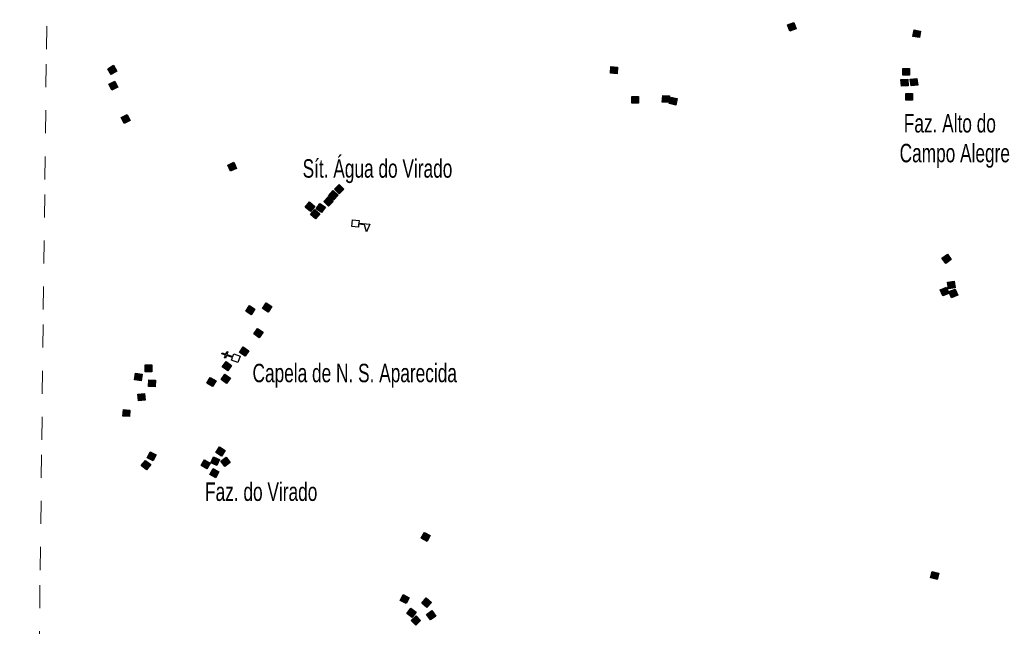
# Model space of a CAD drawing. Extents: x 679 to 705, y 7427.4 to 7455.4.
# Drawn here: x 679.037 to 683.329, y 7434.793 to 7437.424 of the extents above; entities that cross this region are included whole.
import ezdxf

# ---------------------------------------------------------------- set-up
doc = ezdxf.new("R2010")
doc.units = 0
doc.header["$LTSCALE"] = 0.032
doc.linetypes.add('SHORT_DASHED', pattern=[2.7, 1.5, -1.2])
for name, color, linetype, lineweight in [('2', 7, 'Continuous', 25), ('4', 7, 'Continuous', 25), ('58', 7, 'SHORT_DASHED', 13), ('6', 7, 'Continuous', 25)]:
    doc.layers.add(name, color=color, linetype=linetype, lineweight=lineweight)
doc.layers.add('61', color=7, linetype='Continuous')

msp = doc.modelspace()

# ---------------------------------------------------------------- hatches: boundary and pattern name
at = {"layer": '2'}
for points in [[(682.3948, 7437.4121), (682.4052, 7437.385), (682.3782, 7437.3746), (682.3678, 7437.4017)], [(682.9449, 7437.3754), (682.9402, 7437.3468), (682.9116, 7437.3516), (682.9163, 7437.3802)], [(679.4441, 7437.2268), (679.4588, 7437.2019), (679.4338, 7437.1871), (679.4191, 7437.2121)], [(681.6306, 7437.2192), (681.628, 7437.1903), (681.5991, 7437.193), (681.6018, 7437.2218)], [(682.8967, 7437.2135), (682.8967, 7437.1845), (682.8677, 7437.1845), (682.8677, 7437.2135)], [(682.8887, 7437.1666), (682.8907, 7437.1377), (682.8618, 7437.1356), (682.8597, 7437.1645)], [(682.9002, 7437.1664), (682.929, 7437.1697), (682.9323, 7437.1409), (682.9035, 7437.1376)], [(679.45, 7437.1575), (679.4624, 7437.1312), (679.4362, 7437.1188), (679.4238, 7437.145)], [(681.7208, 7437.0912), (681.7208, 7437.0622), (681.6918, 7437.0622), (681.6918, 7437.0912)], [(681.8551, 7437.0944), (681.8532, 7437.0655), (681.8243, 7437.0674), (681.8262, 7437.0964)], [(681.8894, 7437.0821), (681.8828, 7437.0539), (681.8546, 7437.0604), (681.8611, 7437.0887)], [(682.9094, 7437.1038), (682.9094, 7437.0748), (682.8804, 7437.0748), (682.8804, 7437.1038)], [(679.5032, 7437.0127), (679.5158, 7436.9866), (679.4897, 7436.974), (679.4771, 7437.0001)], [(679.9661, 7436.8058), (679.9779, 7436.7793), (679.9514, 7436.7675), (679.9396, 7436.794)], [(680.4223, 7436.7096), (680.4431, 7436.6893), (680.4228, 7436.6685), (680.4021, 7436.6888)], [(680.3757, 7436.6561), (680.3967, 7436.6361), (680.3767, 7436.6151), (680.3557, 7436.6351)], [(680.396, 7436.6828), (680.4178, 7436.6636), (680.3987, 7436.6419), (680.3769, 7436.661)], [(680.2946, 7436.6336), (680.3166, 7436.6147), (680.2977, 7436.5927), (680.2757, 7436.6115)], [(680.3391, 7436.6277), (680.3629, 7436.6111), (680.3463, 7436.5873), (680.3225, 7436.6039)], [(680.3174, 7436.6012), (680.3391, 7436.5821), (680.3199, 7436.5603), (680.2982, 7436.5795)], [(683.0609, 7436.4071), (683.0778, 7436.3835), (683.0542, 7436.3666), (683.0373, 7436.3902)], [(683.0566, 7436.264), (683.0679, 7436.2372), (683.0411, 7436.226), (683.0299, 7436.2527)], [(683.0901, 7436.29), (683.0949, 7436.2614), (683.0663, 7436.2565), (683.0615, 7436.2851)], [(683.0948, 7436.2554), (683.1057, 7436.2286), (683.0788, 7436.2176), (683.0679, 7436.2445)], [(680.0335, 7436.1845), (680.0575, 7436.1682), (680.0412, 7436.1442), (680.0172, 7436.1605)], [(680.1057, 7436.1955), (680.1304, 7436.1804), (680.1153, 7436.1556), (680.0905, 7436.1707)], [(680.0689, 7436.0847), (680.0927, 7436.068), (680.076, 7436.0443), (680.0523, 7436.061)], [(680.0066, 7436.0045), (680.0308, 7435.9884), (680.0147, 7435.9642), (679.9906, 7435.9803)], [(679.6097, 7435.9263), (679.6097, 7435.8973), (679.5807, 7435.8973), (679.5807, 7435.9263)], [(679.933, 7435.9414), (679.9564, 7435.9242), (679.9392, 7435.9008), (679.9159, 7435.918)], [(679.5677, 7435.8867), (679.5643, 7435.8579), (679.5355, 7435.8613), (679.5389, 7435.8901)], [(679.9273, 7435.8865), (679.9508, 7435.8695), (679.9338, 7435.846), (679.9103, 7435.863)], [(679.6258, 7435.861), (679.6244, 7435.832), (679.5955, 7435.8334), (679.5968, 7435.8623)], [(679.8638, 7435.8721), (679.8887, 7435.8572), (679.8738, 7435.8323), (679.8489, 7435.8471)], [(679.5789, 7435.8023), (679.5815, 7435.7735), (679.5526, 7435.7708), (679.55, 7435.7997)], [(679.5154, 7435.7309), (679.5126, 7435.7021), (679.4838, 7435.7048), (679.4866, 7435.7337)], [(679.6029, 7435.5496), (679.6286, 7435.5363), (679.6153, 7435.5105), (679.5895, 7435.5239)], [(679.9042, 7435.5713), (679.9283, 7435.5552), (679.9123, 7435.5311), (679.8881, 7435.5471)], [(679.5825, 7435.5125), (679.6053, 7435.4946), (679.5875, 7435.4718), (679.5646, 7435.4896)], [(679.8389, 7435.5149), (679.8636, 7435.4996), (679.8484, 7435.475), (679.8237, 7435.4902)], [(679.877, 7435.5281), (679.9036, 7435.5166), (679.8921, 7435.4899), (679.8655, 7435.5014)], [(679.9332, 7435.5266), (679.9506, 7435.5033), (679.9274, 7435.486), (679.91, 7435.5092)], [(679.8757, 7435.4766), (679.9013, 7435.4629), (679.8876, 7435.4373), (679.862, 7435.451)], [(680.7923, 7435.1998), (680.8178, 7435.1861), (680.8041, 7435.1605), (680.7786, 7435.1742)], [(682.9956, 7435.0305), (683.0237, 7435.0231), (683.0163, 7434.9951), (682.9883, 7435.0024)], [(680.7008, 7434.9298), (680.7265, 7434.9162), (680.7129, 7434.8906), (680.6873, 7434.9041)], [(680.8006, 7434.9152), (680.8226, 7434.8963), (680.8037, 7434.8743), (680.7817, 7434.8932)], [(680.7331, 7434.8714), (680.7565, 7434.8542), (680.7393, 7434.8309), (680.7159, 7434.8481)], [(680.8247, 7434.8603), (680.8419, 7434.8369), (680.8185, 7434.8197), (680.8013, 7434.8431)], [(680.7563, 7434.8379), (680.7762, 7434.8168), (680.755, 7434.7969), (680.7352, 7434.8181)]]:
    msp.add_hatch(color=256, dxfattribs=at).paths.add_polyline_path(points)

# ---------------------------------------------------------------- linework, layer by layer
for points in [[(682.3948, 7437.4121), (682.4052, 7437.385), (682.3782, 7437.3746), (682.3678, 7437.4017)], [(682.9449, 7437.3754), (682.9402, 7437.3468), (682.9116, 7437.3516), (682.9163, 7437.3802)], [(679.4441, 7437.2268), (679.4588, 7437.2019), (679.4338, 7437.1871), (679.4191, 7437.2121)], [(681.6306, 7437.2192), (681.628, 7437.1903), (681.5991, 7437.193), (681.6018, 7437.2218)], [(682.8967, 7437.2135), (682.8967, 7437.1845), (682.8677, 7437.1845), (682.8677, 7437.2135)], [(682.8887, 7437.1666), (682.8907, 7437.1377), (682.8618, 7437.1356), (682.8597, 7437.1645)], [(682.9002, 7437.1664), (682.929, 7437.1697), (682.9323, 7437.1409), (682.9035, 7437.1376)], [(679.45, 7437.1575), (679.4624, 7437.1312), (679.4362, 7437.1188), (679.4238, 7437.145)], [(681.7208, 7437.0912), (681.7208, 7437.0622), (681.6918, 7437.0622), (681.6918, 7437.0912)], [(681.8551, 7437.0944), (681.8532, 7437.0655), (681.8243, 7437.0674), (681.8262, 7437.0964)], [(681.8894, 7437.0821), (681.8828, 7437.0539), (681.8546, 7437.0604), (681.8611, 7437.0887)], [(682.9094, 7437.1038), (682.9094, 7437.0748), (682.8804, 7437.0748), (682.8804, 7437.1038)], [(679.5032, 7437.0127), (679.5158, 7436.9866), (679.4897, 7436.974), (679.4771, 7437.0001)], [(679.9661, 7436.8058), (679.9779, 7436.7793), (679.9514, 7436.7675), (679.9396, 7436.794)], [(680.4223, 7436.7096), (680.4431, 7436.6893), (680.4228, 7436.6685), (680.4021, 7436.6888)], [(680.3757, 7436.6561), (680.3967, 7436.6361), (680.3767, 7436.6151), (680.3557, 7436.6351)], [(680.396, 7436.6828), (680.4178, 7436.6636), (680.3987, 7436.6419), (680.3769, 7436.661)], [(680.2946, 7436.6336), (680.3166, 7436.6147), (680.2977, 7436.5927), (680.2757, 7436.6115)], [(680.3391, 7436.6277), (680.3629, 7436.6111), (680.3463, 7436.5873), (680.3225, 7436.6039)], [(680.3174, 7436.6012), (680.3391, 7436.5821), (680.3199, 7436.5603), (680.2982, 7436.5795)], [(683.0609, 7436.4071), (683.0778, 7436.3835), (683.0542, 7436.3666), (683.0373, 7436.3902)], [(683.0566, 7436.264), (683.0679, 7436.2372), (683.0411, 7436.226), (683.0299, 7436.2527)], [(683.0901, 7436.29), (683.0949, 7436.2614), (683.0663, 7436.2565), (683.0615, 7436.2851)], [(683.0948, 7436.2554), (683.1057, 7436.2286), (683.0788, 7436.2176), (683.0679, 7436.2445)], [(680.0335, 7436.1845), (680.0575, 7436.1682), (680.0412, 7436.1442), (680.0172, 7436.1605)], [(680.1057, 7436.1955), (680.1304, 7436.1804), (680.1153, 7436.1556), (680.0905, 7436.1707)], [(680.0689, 7436.0847), (680.0927, 7436.068), (680.076, 7436.0443), (680.0523, 7436.061)], [(680.0066, 7436.0045), (680.0308, 7435.9884), (680.0147, 7435.9642), (679.9906, 7435.9803)], [(679.6097, 7435.9263), (679.6097, 7435.8973), (679.5807, 7435.8973), (679.5807, 7435.9263)], [(679.933, 7435.9414), (679.9564, 7435.9242), (679.9392, 7435.9008), (679.9159, 7435.918)], [(679.5677, 7435.8867), (679.5643, 7435.8579), (679.5355, 7435.8613), (679.5389, 7435.8901)], [(679.9273, 7435.8865), (679.9508, 7435.8695), (679.9338, 7435.846), (679.9103, 7435.863)], [(679.6258, 7435.861), (679.6244, 7435.832), (679.5955, 7435.8334), (679.5968, 7435.8623)], [(679.8638, 7435.8721), (679.8887, 7435.8572), (679.8738, 7435.8323), (679.8489, 7435.8471)], [(679.5789, 7435.8023), (679.5815, 7435.7735), (679.5526, 7435.7708), (679.55, 7435.7997)], [(679.5154, 7435.7309), (679.5126, 7435.7021), (679.4838, 7435.7048), (679.4866, 7435.7337)], [(679.6029, 7435.5496), (679.6286, 7435.5363), (679.6153, 7435.5105), (679.5895, 7435.5239)], [(679.9042, 7435.5713), (679.9283, 7435.5552), (679.9123, 7435.5311), (679.8881, 7435.5471)], [(679.5825, 7435.5125), (679.6053, 7435.4946), (679.5875, 7435.4718), (679.5646, 7435.4896)], [(679.8389, 7435.5149), (679.8636, 7435.4996), (679.8484, 7435.475), (679.8237, 7435.4902)], [(679.877, 7435.5281), (679.9036, 7435.5166), (679.8921, 7435.4899), (679.8655, 7435.5014)], [(679.9332, 7435.5266), (679.9506, 7435.5033), (679.9274, 7435.486), (679.91, 7435.5092)], [(679.8757, 7435.4766), (679.9013, 7435.4629), (679.8876, 7435.4373), (679.862, 7435.451)], [(680.7923, 7435.1998), (680.8178, 7435.1861), (680.8041, 7435.1605), (680.7786, 7435.1742)], [(682.9956, 7435.0305), (683.0237, 7435.0231), (683.0163, 7434.9951), (682.9883, 7435.0024)], [(680.7008, 7434.9298), (680.7265, 7434.9162), (680.7129, 7434.8906), (680.6873, 7434.9041)], [(680.8006, 7434.9152), (680.8226, 7434.8963), (680.8037, 7434.8743), (680.7817, 7434.8932)], [(680.7331, 7434.8714), (680.7565, 7434.8542), (680.7393, 7434.8309), (680.7159, 7434.8481)], [(680.8247, 7434.8603), (680.8419, 7434.8369), (680.8185, 7434.8197), (680.8013, 7434.8431)], [(680.7563, 7434.8379), (680.7762, 7434.8168), (680.755, 7434.7969), (680.7352, 7434.8181)]]:
    msp.add_lwpolyline(points, close=True, dxfattribs=at)
at = {"layer": '4'}
for points in [[(680.5071, 7436.5369), (680.5059, 7436.5248), (680.4771, 7436.5277), (680.4799, 7436.5565), (680.5088, 7436.5537), (680.5076, 7436.5418)], [(680.5076, 7436.5418), (680.5558, 7436.537), (680.5409, 7436.5044), (680.5331, 7436.5343), (680.5071, 7436.5369)]]:
    msp.add_lwpolyline(points, dxfattribs=at)
at = {"layer": '58'}
msp.add_lwpolyline([(679.0374, 7427.6915), (679.0442, 7428.2565), (679.051, 7428.8215), (679.0578, 7429.3865), (679.0646, 7429.9515), (679.0714, 7430.5166), (679.0782, 7431.0816), (679.085, 7431.6466), (679.0918, 7432.2116), (679.0986, 7432.7766), (679.1054, 7433.3416), (679.1122, 7433.9066), (679.119, 7434.4716), (679.1258, 7435.0366), (679.1326, 7435.6016), (679.1394, 7436.1666), (679.1462, 7436.7316), (679.153, 7437.2966), (679.1598, 7437.8616), (679.1666, 7438.4266), (679.1734, 7438.9916), (679.1802, 7439.5566), (679.1869, 7440.1216)], dxfattribs=at)
at = {"layer": '6'}
for points in [[(679.9597, 7435.9587), (679.9342, 7435.9677), (679.9302, 7435.9563), (679.9255, 7435.958), (679.9296, 7435.9694), (679.9141, 7435.9748), (679.9157, 7435.9794), (679.9312, 7435.9739), (679.9352, 7435.9853), (679.9399, 7435.9837), (679.9358, 7435.9722), (679.9614, 7435.9632)], [(679.9614, 7435.9632), (679.9654, 7435.9746), (679.9927, 7435.9649), (679.983, 7435.9376), (679.9557, 7435.9473), (679.9597, 7435.9587)]]:
    msp.add_lwpolyline(points, dxfattribs=at)

# ---------------------------------------------------------------- texts
at = {"layer": '61', "width": 0.7}
for s, p in [('Faz. Alto do', (682.8719, 7436.9352)), ('Campo Alegre', (682.8538, 7436.8059)), ('Sít. Água do Virado', (680.2642, 7436.7391)), ('Capela de N. S. Aparecida', (680.0469, 7435.8515)), ('Faz. do Virado', (679.841, 7435.3364))]:
    msp.add_text(s, height=0.08, dxfattribs=at).set_placement(p)

doc.saveas('drawing.dxf')
